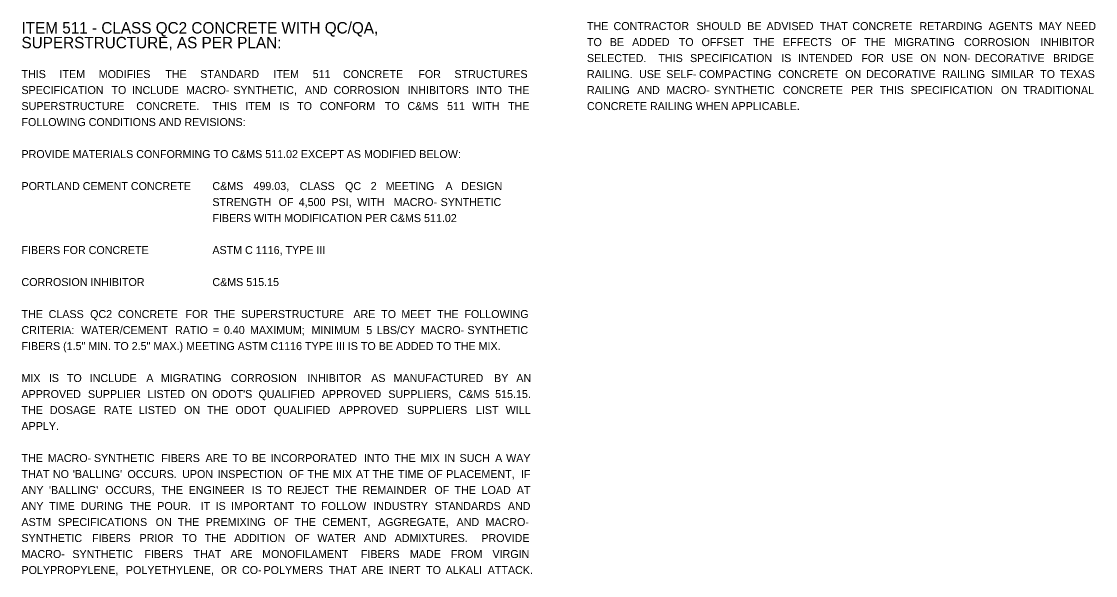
# Model space of a CAD drawing. Extents: x -20.1 to 34, y 0 to 22.
# Drawn here: x -20.11 to -1.31, y 11.45 to 21.15 of the extents above; entities that cross this region are included whole.
import ezdxf

# ---------------------------------------------------------------- set-up
doc = ezdxf.new("R2010")
doc.units = 0
for name, color, linetype in [('BR_P_Gen_Text', 7, 'Continuous'), ('SH_Text', 7, 'Continuous'), ('SN_P_Cantilever_Overhead', 7, 'Continuous')]:
    doc.layers.add(name, color=color, linetype=linetype)

msp = doc.modelspace()

# ---------------------------------------------------------------- texts
at = {"layer": 'BR_P_Gen_Text'}
for s, p in [('ITEM 511 - CLASS QC2 CONCRETE WITH QC/QA, ', (-20.105, 20.94)), ('SUPERSTRUCTURE, AS PER PLAN:', (-20.105, 20.681))]:
    msp.add_text(s, height=0.2, dxfattribs=at).set_placement(p)
at = {"layer": 'SH_Text'}
for s, p in [('THE ', (-10.212, 21)), ('CONTRACTOR ', (-9.747, 21)), ('SHOULD ', (-8.296, 21)), ('BE ', (-7.407, 21)), ('ADVISED ', (-7.071, 21)), ('THAT ', (-6.138, 21)), ('CONCRETE ', (-5.568, 21)), ('RETARDING ', (-4.396, 21)), ('AGENTS ', (-3.184, 21)), ('MAY ', (-2.306, 21)), ('NEED ', (-1.826, 21)), ('TO ', (-10.212, 20.72)), ('BE ', (-9.813, 20.72)), ('ADDED ', (-9.422, 20.72)), ('TO ', (-8.606, 20.72)), ('OFFSET ', (-8.207, 20.72)), ('THE ', (-7.305, 20.72)), ('EFFECTS ', (-6.783, 20.72)), ('OF ', (-5.761, 20.72)), ('THE ', (-5.362, 20.72)), ('MIGRATING ', (-4.84, 20.72)), ('CORROSION ', (-3.616, 20.72)), ('INHIBITOR ', (-2.278, 20.72)), ('SELECTED.  ', (-10.212, 20.44)), ('THIS ', (-8.962, 20.44)), ('SPECIFICATION ', (-8.408, 20.44)), ('IS ', (-6.814, 20.44)), ('INTENDED ', (-6.521, 20.44)), ('FOR ', (-5.412, 20.44)), ('USE ', (-4.89, 20.44)), ('ON ', (-4.38, 20.44)), ('NON-', (-3.978, 20.44)), ('DECORATIVE ', (-3.424, 20.44)), ('BRIDGE ', (-2.058, 20.44)), ('THIS ', (-20.105, 20.16)), ('ITEM ', (-19.44, 20.16)), ('MODIFIES ', (-18.754, 20.16)), ('THE ', (-17.589, 20.16)), ('STANDARD ', (-16.978, 20.16)), ('ITEM ', (-15.697, 20.16)), ('511 ', (-15.01, 20.16)), ('CONCRETE ', (-14.479, 20.16)), ('FOR ', (-13.162, 20.16)), ('STRUCTURES ', (-12.53, 20.16)), ('RAILING. ', (-10.212, 20.16)), ('USE ', (-9.301, 20.16)), ('SELF-', (-8.825, 20.16)), ('COMPACTING ', (-8.251, 20.16)), ('CONCRETE ', (-6.866, 20.16)), ('ON ', (-5.694, 20.16)), ('DECORATIVE ', (-5.327, 20.16)), ('RAILING ', (-3.996, 20.16)), ('SIMILAR ', (-3.14, 20.16)), ('TO ', (-2.283, 20.16)), ('TEXAS ', (-1.941, 20.16)), ('SPECIFICATION ', (-20.105, 19.88)), ('TO ', (-18.531, 19.88)), ('INCLUDE ', (-18.174, 19.88)), ('MACRO-', (-17.227, 19.88)), ('SYNTHETIC, ', (-16.399, 19.88)), ('AND ', (-15.147, 19.88)), ('CORROSION ', (-14.645, 19.88)), ('INHIBITORS ', (-13.35, 19.88)), ('INTO ', (-12.145, 19.88)), ('THE ', (-11.592, 19.88)), ('RAILING ', (-10.212, 19.88)), ('AND ', (-9.333, 19.88)), ('MACRO-', (-8.824, 19.88)), ('SYNTHETIC ', (-7.989, 19.88)), ('CONCRETE ', (-6.784, 19.88)), ('PER ', (-5.59, 19.88)), ('THIS ', (-5.092, 19.88)), ('SPECIFICATION ', (-4.55, 19.88)), ('ON ', (-2.968, 19.88)), ('TRADITIONAL ', (-2.579, 19.88)), ('SUPERSTRUCTURE ', (-20.105, 19.6)), ('CONCRETE.  ', (-18.097, 19.6)), ('THIS ', (-16.763, 19.6)), ('ITEM ', (-16.19, 19.6)), ('IS ', (-15.595, 19.6)), ('TO ', (-15.282, 19.6)), ('CONFORM ', (-14.886, 19.6)), ('TO ', (-13.748, 19.6)), ('C&MS ', (-13.352, 19.6)), ('511 ', (-12.659, 19.6)), ('WITH ', (-12.22, 19.6)), ('THE ', (-11.592, 19.6)), ('CONCRETE RAILING WHEN APPLICABLE.', (-10.212, 19.6)), ('FOLLOWING CONDITIONS AND REVISIONS:', (-20.105, 19.32)), ('PROVIDE MATERIALS CONFORMING TO C&MS 511.02 EXCEPT AS MODIFIED BELOW:', (-20.105, 18.76)), ('PORTLAND CEMENT CONCRETE', (-20.105, 18.2)), ('FIBERS FOR CONCRETE', (-20.105, 17.08)), ('CORROSION INHIBITOR', (-20.105, 16.52)), ('THE ', (-20.105, 15.96)), ('CLASS ', (-19.63, 15.96)), ('QC2 ', (-18.904, 15.96)), ('CONCRETE ', (-18.418, 15.96)), ('FOR ', (-17.236, 15.96)), ('THE ', (-16.739, 15.96)), ('SUPERSTRUCTURE ', (-16.263, 15.96)), ('ARE ', (-14.298, 15.96)), ('TO ', (-13.812, 15.96)), ('MEET ', (-13.459, 15.96)), ('THE ', (-12.832, 15.96)), ('FOLLOWING ', (-12.356, 15.96)), ('CRITERIA: ', (-20.105, 15.68)), ('WATER/CEMENT ', (-19.061, 15.68)), ('RATIO ', (-17.416, 15.68)), ('0.40 ', (-16.564, 15.68)), ('MAXIMUM; ', (-16.107, 15.68)), ('MINIMUM ', (-15.03, 15.68)), ('5 ', (-14.073, 15.68)), ('LBS/CY ', (-13.888, 15.68)), ('MACRO-', (-13.118, 15.68)), ('SYNTHETIC ', (-12.302, 15.68)), ('= ', (-16.755, 15.68)), ('FIBERS (1.5" MIN. TO 2.5" MAX.) MEETING ASTM C1116 TYPE III IS TO BE ADDED TO THE MIX.', (-20.105, 15.4)), ('MIX ', (-20.105, 14.84)), ('IS ', (-19.626, 14.84)), ('TO ', (-19.31, 14.84)), ('INCLUDE ', (-18.911, 14.84)), ('A ', (-17.921, 14.84)), ('MIGRATING ', (-17.667, 14.84)), ('CORROSION ', (-16.441, 14.84)), ('INHIBITOR ', (-15.104, 14.84)), ('AS ', (-13.987, 14.84)), ('MANUFACTURED ', (-13.595, 14.84)), ('BY ', (-11.837, 14.84)), ('AN ', (-11.448, 14.84)), ('APPROVED ', (-20.105, 14.56)), ('SUPPLIER ', (-18.942, 14.56)), ('LISTED ', (-17.899, 14.56)), ('ON ', (-17.138, 14.56)), ("ODOT'S ", (-16.768, 14.56)), ('QUALIFIED ', (-15.959, 14.56)), ('APPROVED ', (-14.851, 14.56)), ('SUPPLIERS, ', (-13.687, 14.56)), ('C&MS ', (-12.459, 14.56)), ('515.15.    ', (-11.818, 14.56)), ('THE ', (-20.105, 14.28)), ('DOSAGE ', (-19.608, 14.28)), ('RATE ', (-18.664, 14.28)), ('LISTED ', (-18.051, 14.28)), ('ON ', (-17.26, 14.28)), ('THE ', (-16.86, 14.28)), ('ODOT ', (-16.363, 14.28)), ('QUALIFIED ', (-15.691, 14.28)), ('APPROVED ', (-14.552, 14.28)), ('SUPPLIERS ', (-13.359, 14.28)), ('LIST ', (-12.154, 14.28)), ('WILL ', (-11.635, 14.28)), ('APPLY.  ', (-20.105, 14)), ('THE ', (-20.105, 13.44)), ('MACRO-', (-19.645, 13.44)), ('SYNTHETIC ', (-18.837, 13.44)), ('FIBERS ', (-17.66, 13.44)), ('ARE ', (-16.884, 13.44)), ('TO ', (-16.413, 13.44)), ('BE ', (-16.076, 13.44)), ('INCORPORATED ', (-15.746, 13.44)), ('INTO ', (-14.115, 13.44)), ('THE ', (-13.583, 13.44)), ('MIX ', (-13.123, 13.44)), ('IN ', (-12.706, 13.44)), ('SUCH ', (-12.441, 13.44)), ('A ', (-11.818, 13.44)), ('WAY ', (-11.626, 13.44)), ('THAT ', (-20.105, 13.16)), ('NO ', (-19.555, 13.16)), ("'BALLING' ", (-19.207, 13.16)), ('OCCURS. ', (-18.251, 13.16)), ('UPON ', (-17.294, 13.16)), ('INSPECTION ', (-16.675, 13.16)), ('OF ', (-15.424, 13.16)), ('THE ', (-15.102, 13.16)), ('MIX ', (-14.656, 13.16)), ('AT ', (-14.253, 13.16)), ('THE ', (-13.963, 13.16)), ('TIME ', (-13.517, 13.16)), ('OF ', (-12.996, 13.16)), ('PLACEMENT, ', (-12.673, 13.16)), ('IF ', (-11.368, 13.16)), ('ANY ', (-20.105, 12.88)), ("'BALLING' ", (-19.624, 12.88)), ('OCCURS, ', (-18.64, 12.88)), ('THE ', (-17.654, 12.88)), ('ENGINEER ', (-17.18, 12.88)), ('IS ', (-16.075, 12.88)), ('TO ', (-15.807, 12.88)), ('REJECT ', (-15.456, 12.88)), ('THE ', (-14.612, 12.88)), ('REMAINDER ', (-14.138, 12.88)), ('OF ', (-12.881, 12.88)), ('THE ', (-12.53, 12.88)), ('LOAD ', (-12.055, 12.88)), ('AT ', (-11.44, 12.88)), ('ANY ', (-20.105, 12.6)), ('TIME ', (-19.62, 12.6)), ('DURING ', (-19.066, 12.6)), ('THE ', (-18.208, 12.6)), ('POUR.  ', (-17.73, 12.6)), ('IT ', (-16.97, 12.6)), ('IS ', (-16.709, 12.6)), ('IMPORTANT ', (-16.438, 12.6)), ('TO ', (-15.217, 12.6)), ('FOLLOW ', (-14.863, 12.6)), ('INDUSTRY ', (-13.95, 12.6)), ('STANDARDS ', (-12.875, 12.6)), ('AND ', (-11.596, 12.6)), ('ASTM ', (-20.105, 12.32)), ('SPECIFICATIONS ', (-19.467, 12.32)), ('ON ', (-17.757, 12.32)), ('THE ', (-17.369, 12.32)), ('PREMIXING ', (-16.883, 12.32)), ('OF ', (-15.691, 12.32)), ('THE ', (-15.328, 12.32)), ('CEMENT, ', (-14.842, 12.32)), ('AGGREGATE, ', (-13.867, 12.32)), ('AND ', (-12.493, 12.32)), ('MACRO-', (-11.986, 12.32)), ('SYNTHETIC ', (-20.105, 12.04)), ('FIBERS ', (-18.871, 12.04)), ('PRIOR ', (-18.039, 12.04)), ('TO ', (-17.294, 12.04)), ('THE ', (-16.9, 12.04)), ('ADDITION ', (-16.383, 12.04)), ('OF ', (-15.323, 12.04)), ('WATER ', (-14.929, 12.04)), ('AND ', (-14.115, 12.04)), ('ADMIXTURES.  ', (-13.577, 12.04)), ('PROVIDE ', (-12.06, 12.04)), ('MACRO-', (-20.105, 11.76)), ('SYNTHETIC ', (-19.215, 11.76)), ('FIBERS ', (-17.955, 11.76)), ('THAT ', (-17.096, 11.76)), ('ARE ', (-16.449, 11.76)), ('MONOFILAMENT ', (-15.895, 11.76)), ('FIBERS ', (-14.167, 11.76)), ('MADE ', (-13.309, 11.76)), ('FROM ', (-12.592, 11.76)), ('VIRGIN ', (-11.865, 11.76)), ('POLYPROPYLENE, ', (-20.105, 11.48)), ('POLYETHYLENE, ', (-18.278, 11.48)), ('OR ', (-16.614, 11.48)), ('CO-', (-16.247, 11.48)), ('POLYMERS ', (-15.87, 11.48)), ('THAT ', (-14.727, 11.48)), ('ARE ', (-14.158, 11.48)), ('INERT ', (-13.682, 11.48)), ('TO ', (-13.026, 11.48)), ('ALKALI ', (-12.684, 11.48)), ('ATTACK.  ', (-11.948, 11.48))]:
    msp.add_text(s, height=0.14, dxfattribs=at).set_placement(p)
at = {"layer": 'SN_P_Cantilever_Overhead'}
for s, p in [('C&MS ', (-16.765, 18.2)), ('499.03, ', (-16.046, 18.2)), ('CLASS ', (-15.239, 18.2)), ('QC ', (-14.444, 18.2)), ('2 ', (-13.996, 18.2)), ('MEETING ', (-13.733, 18.2)), ('A ', (-12.688, 18.2)), ('DESIGN ', (-12.411, 18.2)), ('STRENGTH ', (-16.765, 17.92)), ('OF ', (-15.606, 17.92)), ('4,500 ', (-15.255, 17.92)), ('PSI, ', (-14.683, 17.92)), ('WITH  ', (-14.231, 17.92)), ('MACRO-', (-13.594, 17.92)), ('SYNTHETIC ', (-12.772, 17.92)), ('FIBERS WITH MODIFICATION PER C&MS 511.02', (-16.765, 17.64)), ('ASTM C 1116, TYPE III', (-16.765, 17.08)), ('C&MS 515.15', (-16.765, 16.52))]:
    msp.add_text(s, height=0.14, dxfattribs=at).set_placement(p)

doc.saveas('drawing.dxf')
